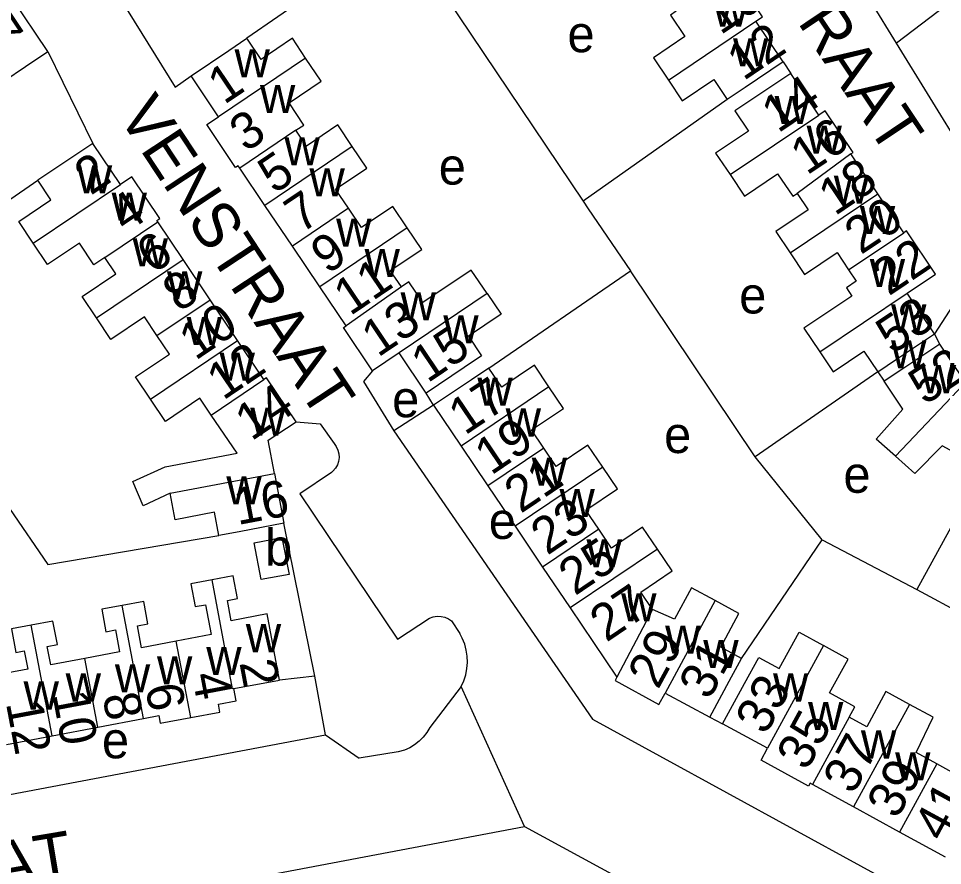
# Model space of a CAD drawing. Extents: x 158356 to 159894, y 383831 to 385260.
# Drawn here: x 158792.4 to 158893.5, y 384070.1 to 384162.8 of the extents above; entities that cross this region are included whole.
import ezdxf

# ---------------------------------------------------------------- set-up
doc = ezdxf.new("R2010")
doc.units = 0
for name, color, linetype in [('BLT_Basislijn', 7, 'Continuous'), ('BLT_Bebouwing', 7, 'Continuous'), ('BLT_Centroide', 7, 'Continuous'), ('BLT_Huisnummer', 7, 'Continuous'), ('BLT_Huisnummer_ tussenligend', 7, 'Continuous'), ('BLT_Onderdoorgang_en_onderverdeling', 7, 'Continuous'), ('BLT_Onderverdeling_panden', 7, 'Continuous'), ('BLT_Straatnaam', 7, 'Continuous'), ('BLT_Vlakafsluiter', 7, 'Continuous')]:
    doc.layers.add(name, color=color, linetype=linetype)

msp = doc.modelspace()

# ---------------------------------------------------------------- linework, layer by layer
at = {"layer": 'BLT_Basislijn'}
for p, q in [((158835.86, 384170.1), (158854.18, 384142.81)), ((158888.48, 384160.12), (158885.74, 384164.57)), ((158896.12, 384147.7), (158888.48, 384160.12)), ((158795.59, 384159.2), (158800.5, 384149.14)), ((158876.08, 384158.06), (158876.9, 384156.81)), ((158869.96, 384153.95), (158854.18, 384142.81)), ((158843.85, 384124.55), (158859.36, 384135.19)), ((158837.8, 384120.48), (158837.01, 384121.81)), ((158837.8, 384120.48), (158833.44, 384117.69)), ((158822.77, 384118.68), (158825.38, 384118.43)), ((158825.38, 384118.43), (158826.91, 384116.3)), ((158880.34, 384105.75), (158873, 384114.85)), ((158897.99, 384113.6), (158890.7, 384100.31)), ((158824.81, 384090.82), (158821.43, 384107.57)), ((158871.51, 384092.76), (158880.34, 384105.75)), ((158880.34, 384105.75), (158890.7, 384100.31)), ((158890.7, 384100.31), (158920.54, 384084.28)), ((158839.78, 384096.87), (158840.67, 384095.5)), ((158824.81, 384090.82), (158820.93, 384090.4)), ((158825.97, 384084.41), (158824.81, 384090.82)), ((158840.81, 384089.71), (158837.38, 384085.21)), ((158868.03, 384086.34), (158869.45, 384085.62)), ((158770.26, 384073.85), (158825.97, 384084.41)), ((158825.97, 384084.41), (158829.66, 384081.86)), ((158833.93, 384082.55), (158829.66, 384081.86))]:
    msp.add_line(p, q, dxfattribs=at)
for points in [[(158908.13, 384178.98), (158909.41, 384176.35), (158909.32, 384175.99), (158888.48, 384160.12)], [(158835.86, 384170.1), (158834.33, 384172.38), (158817.37, 384160.65)], [(158801.39, 384168.44), (158809.52, 384155.32), (158811.27, 384156.54)], [(158776.55, 384133.1), (158779.21, 384134.56), (158794.5, 384145.11)], [(158854.18, 384142.81), (158854.74, 384141.98), (158859.36, 384135.19)], [(158873, 384114.85), (158859.36, 384135.19)], [(158831.12, 384124.26), (158830.13, 384123.07), (158833.44, 384117.69)], [(158886.43, 384124.13), (158873, 384114.85)], [(158833.44, 384117.69), (158855.2, 384086.11), (158906.53, 384058.02)], [(158826.91, 384116.3), (158827.15, 384115.96), (158827.33, 384115.58), (158827.43, 384115.17), (158827.46, 384114.76), (158827.4, 384114.34), (158827.27, 384113.95), (158827.06, 384113.58), (158826.79, 384113.26), (158826.63, 384113.13)], [(158826.63, 384113.13), (158823.17, 384110.77), (158833.87, 384094.88), (158837.35, 384097.19)], [(158791.37, 384109.19), (158795.56, 384103.06), (158814.31, 384106.22)], [(158837.35, 384097.19), (158837.76, 384097.33), (158838.19, 384097.39), (158838.63, 384097.37), (158839.05, 384097.27), (158839.45, 384097.1), (158839.78, 384096.87)], [(158840.81, 384089.71), (158841.1, 384090.33), (158841.32, 384090.98), (158841.45, 384091.65), (158841.51, 384092.33), (158841.49, 384093.01), (158841.39, 384093.68), (158841.21, 384094.34), (158840.95, 384094.97), (158840.67, 384095.5)], [(158837.38, 384085.21), (158837.06, 384084.66), (158836.67, 384084.16), (158836.23, 384083.71), (158835.73, 384083.32), (158835.19, 384082.99), (158834.61, 384082.74), (158833.93, 384082.55)], [(158810.66, 384061.72), (158809.81, 384066.33), (158809.81, 384066.91), (158810.54, 384067.32), (158847.76, 384074.35)], [(158847.76, 384074.35), (158872.31, 384061.02)]]:
    msp.add_lwpolyline(points, dxfattribs=at)
at = {"layer": 'BLT_Bebouwing'}
for p, q in [((158795.59, 384159.2), (158788.57, 384169.69)), ((158876.08, 384158.06), (158873.09, 384162.52)), ((158814.27, 384152.07), (158811.27, 384156.54)), ((158879.97, 384152.25), (158876.9, 384156.81)), ((158803.52, 384144.66), (158800.5, 384149.14)), ((158886.44, 384143.61), (158883.5, 384147.99)), ((158819.35, 384142.36), (158816.6, 384146.44)), ((158889.29, 384139.37), (158886.44, 384143.61)), ((158822.35, 384137.9), (158819.35, 384142.36)), ((158801.82, 384136.66), (158807.62, 384140.55)), ((158810.4, 384136.42), (158807.62, 384140.55)), ((158825.35, 384133.45), (158822.35, 384137.9)), ((158813.34, 384132.04), (158810.4, 384136.42)), ((158828.23, 384129.18), (158825.35, 384133.45)), ((158892.63, 384128.3), (158889.65, 384132.74)), ((158816.34, 384127.56), (158813.34, 384132.04)), ((158893.24, 384127.17), (158892.63, 384128.3)), ((158819.22, 384123.29), (158816.34, 384127.56)), ((158896.02, 384122.99), (158893.24, 384127.17)), ((158834.04, 384126.22), (158831.12, 384124.26)), ((158837.01, 384121.81), (158834.04, 384126.22)), ((158886.43, 384124.13), (158887.13, 384123.11)), ((158837.8, 384120.48), (158840.81, 384116.02)), ((158840.81, 384116.02), (158843.76, 384111.65)), ((158820.4, 384113.01), (158821.43, 384107.57)), ((158843.76, 384111.65), (158846.72, 384107.25)), ((158846.72, 384107.25), (158849.74, 384102.77)), ((158849.74, 384102.77), (158852.76, 384098.3)), ((158852.76, 384098.3), (158857.88, 384090.7)), ((158863.16, 384088.98), (158868.03, 384086.34)), ((158801.06, 384085.24), (158806.06, 384086.18)), ((158874.36, 384082.94), (158869.45, 384085.62)), ((158796.05, 384084.3), (158801.06, 384085.24)), ((158791.05, 384083.35), (158796.05, 384084.3)), ((158883.77, 384076.51), (158879.27, 384078.97)), ((158888.82, 384073.75), (158883.77, 384076.51)), ((158893.84, 384071), (158888.82, 384073.75))]:
    msp.add_line(p, q, dxfattribs=at)
for points in [[(158873.09, 384162.52), (158873.83, 384163.02), (158870.65, 384167.75), (158870.36, 384167.55)], [(158864.38, 384163.62), (158863.75, 384163.19), (158865.32, 384160.84), (158861.87, 384158.52), (158863.51, 384156.08)], [(158811.27, 384156.54), (158815.41, 384159.33), (158817.37, 384160.65)], [(158823.8, 384158.49), (158822.35, 384160.65), (158818.93, 384158.34), (158817.37, 384160.65)], [(158790.77, 384155.97), (158793.15, 384157.57), (158795.59, 384159.2)], [(158822.74, 384150.58), (158823.61, 384151.16), (158821.98, 384153.58), (158825.51, 384155.96), (158823.8, 384158.49)], [(158876.08, 384158.06), (158871.93, 384155.28), (158869.96, 384153.95)], [(158876.9, 384156.81), (158872.76, 384154.02), (158870.79, 384152.7), (158872.27, 384150.5), (158868.68, 384148.09), (158870.27, 384145.74)], [(158863.51, 384156.08), (158865.03, 384153.81), (158868.49, 384156.14), (158869.96, 384153.95)], [(158883.5, 384147.99), (158883.75, 384148.15), (158880.67, 384152.73), (158879.97, 384152.25)], [(158816.6, 384146.44), (158816.42, 384146.71), (158816.13, 384146.52), (158812.98, 384151.2), (158814.27, 384152.07)], [(158828.91, 384148.8), (158827.32, 384151.17), (158823.9, 384148.86), (158822.74, 384150.58)], [(158800.5, 384149.14), (158796.35, 384146.36), (158794.5, 384145.11)], [(158828.5, 384142.05), (158827.08, 384144.14), (158830.5, 384146.44), (158828.91, 384148.8)], [(158807.62, 384140.55), (158807.52, 384140.7), (158807.84, 384140.92), (158804.77, 384145.5), (158803.52, 384144.66)], [(158870.27, 384145.74), (158871.85, 384143.38), (158875.47, 384145.81), (158877.12, 384143.36), (158877.6, 384143.68)], [(158793.98, 384138.24), (158792.4, 384140.59), (158795.92, 384142.96), (158794.5, 384145.11)], [(158877.6, 384143.68), (158878.81, 384141.89), (158875.26, 384139.51), (158876.84, 384137.15)], [(158834.93, 384139.9), (158833.34, 384142.25), (158829.91, 384139.95), (158828.5, 384142.05)], [(158834.28, 384133.43), (158833.07, 384135.23), (158836.51, 384137.55), (158834.93, 384139.9)], [(158889.65, 384132.74), (158892.76, 384134.84), (158889.59, 384139.56), (158889.29, 384139.37)], [(158801.82, 384136.66), (158800.63, 384135.86), (158799.03, 384138.24), (158795.55, 384135.9), (158793.98, 384138.24)], [(158876.84, 384137.15), (158878.42, 384134.8), (158881.97, 384137.19), (158883.24, 384135.3)], [(158800.9, 384130.04), (158799.32, 384132.38), (158803.02, 384134.87), (158801.82, 384136.66)], [(158843.67, 384132.71), (158841.93, 384135.28), (158836.64, 384131.72), (158835.11, 384133.99), (158834.28, 384133.43)], [(158883.24, 384135.3), (158884.08, 384134.05), (158883.01, 384133.33), (158883.6, 384132.44), (158878.35, 384128.91), (158880.09, 384126.32)], [(158843.67, 384132.71), (158845.19, 384130.44), (158841.62, 384128.03), (158843.07, 384125.89), (158841.15, 384124.6), (158837.01, 384121.81)], [(158807.52, 384128.12), (158806.15, 384130.16), (158802.47, 384127.69), (158800.9, 384130.04)], [(158831.12, 384124.26), (158827.94, 384128.99), (158828.23, 384129.18)], [(158806.81, 384121.16), (158805.17, 384123.6), (158808.88, 384126.09), (158807.52, 384128.12)], [(158880.09, 384126.32), (158881.56, 384124.14), (158884.91, 384126.39), (158886.43, 384124.13)], [(158843.85, 384124.55), (158841.95, 384123.27), (158837.8, 384120.48)], [(158850.43, 384122.5), (158848.84, 384124.86), (158845.26, 384122.45), (158843.85, 384124.55)], [(158822.77, 384118.68), (158819.53, 384123.5), (158819.22, 384123.29)], [(158888.37, 384114.89), (158886.25, 384116.78), (158889.17, 384120.04), (158887.13, 384123.11)], [(158849.88, 384115.78), (158848.52, 384117.78), (158852.03, 384120.14), (158850.43, 384122.5)], [(158813.45, 384119.41), (158812.2, 384121.24), (158808.45, 384118.72), (158806.81, 384121.16)], [(158808.98, 384110.85), (158806.01, 384109.47), (158804.9, 384112.15), (158808.43, 384113.75), (158816.3, 384115.24), (158813.45, 384119.41)], [(158820.4, 384113.01), (158819.71, 384116.65), (158822.77, 384118.68)], [(158856.32, 384113.72), (158854.71, 384116.11), (158851.23, 384113.77), (158849.88, 384115.78)], [(158897, 384114.14), (158893.5, 384116.04), (158890.48, 384113), (158888.37, 384114.89)], [(158855.89, 384106.92), (158854.48, 384109), (158857.93, 384111.33), (158856.32, 384113.72)], [(158814.31, 384106.22), (158813.83, 384108.76), (158809.53, 384107.95), (158808.98, 384110.85)], [(158821.43, 384107.57), (158816.51, 384106.64), (158814.31, 384106.22)], [(158862.31, 384104.73), (158860.69, 384107.13), (158857.29, 384104.83), (158855.89, 384106.92)], [(158861.76, 384098.13), (158860.48, 384100.02), (158863.92, 384102.34), (158862.31, 384104.73)], [(158820.93, 384090.4), (158819.57, 384097.63), (158815.64, 384096.89), (158815.23, 384099.1), (158816.34, 384099.31), (158815.87, 384101.81), (158813.56, 384101.37)], [(158813.56, 384101.37), (158811.24, 384100.93), (158811.71, 384098.44), (158812.82, 384098.65), (158813.44, 384095.37), (158809.64, 384094.65)], [(158868.64, 384099.09), (158866.05, 384100.49), (158864.19, 384097.07), (158861.76, 384098.13)], [(158809.64, 384094.65), (158805.84, 384093.93), (158805.39, 384096.34), (158806.53, 384096.55), (158806.07, 384099.01), (158803.72, 384098.57)], [(158871.51, 384092.76), (158869.24, 384094), (158871.24, 384097.68), (158868.64, 384099.09)], [(158803.72, 384098.57), (158801.48, 384098.15), (158801.94, 384095.69), (158802.97, 384095.88), (158803.43, 384093.48), (158799.64, 384092.76)], [(158799.64, 384092.76), (158795.89, 384092.06), (158795.51, 384094.07), (158796.62, 384094.28), (158796.14, 384096.84), (158793.77, 384096.4)], [(158793.77, 384096.4), (158791.59, 384095.99), (158792.07, 384093.42), (158792.99, 384093.6), (158793.37, 384091.58), (158789.63, 384090.88)], [(158869.45, 384085.62), (158871.85, 384090.01), (158873.41, 384092.88), (158875.65, 384091.65), (158877.82, 384095.63), (158880.5, 384094.17)], [(158883.3, 384086.34), (158883.92, 384087.48), (158881.15, 384088.99), (158883.18, 384092.7), (158880.5, 384094.17)], [(158868.03, 384086.34), (158870.41, 384090.74), (158871.51, 384092.76)], [(158857.88, 384090.7), (158857.69, 384090.34), (158862.48, 384087.74), (158863.16, 384088.98)], [(158815.94, 384089.46), (158820.93, 384090.4)], [(158811.22, 384086.3), (158814.41, 384086.9), (158814.25, 384087.76), (158816.2, 384088.13), (158815.94, 384089.46)], [(158889.91, 384087.73), (158887.33, 384089.13), (158885.23, 384085.28), (158883.3, 384086.34)], [(158892.9, 384081.21), (158890.62, 384082.46), (158892.48, 384086.32), (158889.91, 384087.73)], [(158806.06, 384086.18), (158807.73, 384086.5), (158807.89, 384085.67), (158811.22, 384086.3)], [(158900.01, 384082.27), (158897.26, 384083.78), (158895.18, 384079.96), (158892.9, 384081.21)], [(158879.27, 384078.97), (158879.03, 384079.1), (158878.86, 384078.79), (158873.67, 384081.63), (158874.36, 384082.94)]]:
    msp.add_lwpolyline(points, dxfattribs=at)
msp.add_lwpolyline([(158818.17, 384105.42), (158821.21, 384106), (158821.98, 384101.97), (158818.93, 384101.39)], close=True, dxfattribs=at)
at = {"layer": 'BLT_Onderdoorgang_en_onderverdeling'}
for points in [[(158886.43, 384124.13), (158888.48, 384125.51), (158892.63, 384128.3)], [(158893.24, 384127.17), (158889.07, 384124.4), (158887.13, 384123.11)]]:
    msp.add_lwpolyline(points, dxfattribs=at)
at = {"layer": 'BLT_Onderverdeling_panden'}
for p, q in [((158863.51, 384156.08), (158873.09, 384162.52)), ((158823.8, 384158.49), (158814.27, 384152.07)), ((158870.27, 384145.74), (158879.97, 384152.25)), ((158822.74, 384150.58), (158816.6, 384146.44)), ((158828.91, 384148.8), (158819.35, 384142.36)), ((158883.5, 384147.99), (158877.6, 384143.68)), ((158793.98, 384138.24), (158803.52, 384144.66)), ((158876.84, 384137.15), (158886.44, 384143.61)), ((158828.5, 384142.05), (158822.35, 384137.9)), ((158834.93, 384139.9), (158825.35, 384133.45)), ((158883.24, 384135.3), (158889.29, 384139.37)), ((158800.9, 384130.04), (158810.4, 384136.42)), ((158834.28, 384133.43), (158828.23, 384129.18)), ((158843.67, 384132.71), (158834.04, 384126.22)), ((158880.09, 384126.32), (158889.65, 384132.74)), ((158807.52, 384128.12), (158813.34, 384132.04)), ((158806.81, 384121.16), (158816.34, 384127.56)), ((158813.45, 384119.41), (158819.22, 384123.29)), ((158850.43, 384122.5), (158840.81, 384116.02)), ((158888.37, 384114.89), (158896.02, 384122.99)), ((158849.88, 384115.78), (158843.76, 384111.65)), ((158808.98, 384110.85), (158820.4, 384113.01)), ((158856.32, 384113.72), (158846.72, 384107.25)), ((158855.89, 384106.92), (158849.74, 384102.77)), ((158862.31, 384104.73), (158852.76, 384098.3)), ((158868.64, 384099.09), (158863.16, 384088.98)), ((158806.06, 384086.18), (158803.72, 384098.57)), ((158861.76, 384098.13), (158857.88, 384090.7)), ((158796.05, 384084.3), (158793.77, 384096.4)), ((158880.5, 384094.17), (158874.36, 384082.94)), ((158801.06, 384085.24), (158799.64, 384092.76)), ((158889.91, 384087.73), (158883.77, 384076.51)), ((158883.3, 384086.34), (158879.27, 384078.97)), ((158892.9, 384081.21), (158888.82, 384073.75))]:
    msp.add_line(p, q, dxfattribs=at)
for points in [[(158815.94, 384089.46), (158815.81, 384089.44), (158813.56, 384101.37)], [(158811.22, 384086.3), (158809.64, 384094.65)]]:
    msp.add_lwpolyline(points, dxfattribs=at)
at = {"layer": 'BLT_Vlakafsluiter'}
for p, q in [((158900.74, 384140.84), (158892.63, 384128.3)), ((158847.76, 384074.35), (158840.81, 384089.71))]:
    msp.add_line(p, q, dxfattribs=at)

# ---------------------------------------------------------------- texts
at = {"layer": 'BLT_Centroide'}
for s, p in [('w', (158868.4, 384161.91)), ('e', (158852.46, 384159.13)), ('w', (158870.59, 384157.59)), ('w', (158816.02, 384156.38)), ('w', (158818.8, 384152.47)), ('w', (158875.13, 384151.28)), ('w', (158878.64, 384148.03)), ('w', (158821.48, 384146.75)), ('e', (158838.37, 384144.64)), ('w', (158798.76, 384143.69)), ('w', (158824.22, 384143.34)), ('w', (158881.62, 384142.56)), ('w', (158802.56, 384140.69)), ('w', (158884.47, 384139.22)), ('w', (158827.14, 384137.84)), ('w', (158804.86, 384135.69)), ('w', (158830.25, 384134.53)), ('w', (158885.56, 384133.42)), ('w', (158808.62, 384132.06)), ('e', (158871.26, 384130.53)), ('w', (158834.19, 384129.78)), ('w', (158887.89, 384128.44)), ('w', (158810.77, 384127.06)), ('w', (158838.87, 384127.25)), ('w', (158887.89, 384124.51)), ('w', (158814.38, 384123.16)), ('w', (158891.14, 384121.8)), ('w', (158842.6, 384120.44)), ('e', (158833.27, 384119.17)), ('w', (158817.73, 384117.16)), ('w', (158845.7, 384117.06)), ('e', (158863.04, 384115.25)), ('w', (158848.55, 384111.69)), ('e', (158882.67, 384110.9)), ('w', (158815.12, 384109.62)), ('w', (158851.59, 384108.25)), ('e', (158843.85, 384105.85)), ('b', (158819.36, 384102.93)), ('w', (158854.55, 384102.72)), ('w', (158858.34, 384096.81)), ('w', (158817.25, 384093.45)), ('w', (158863.16, 384093.27)), ('w', (158867.33, 384091.7)), ('w', (158812.92, 384090.95)), ('w', (158807.53, 384089.92)), ('w', (158802.92, 384089.05)), ('w', (158797.53, 384088.05)), ('w', (158874.97, 384088.05)), ('w', (158792.92, 384087.17)), ('w', (158878.8, 384084.94)), ('e', (158801.5, 384081.83)), ('w', (158884.59, 384081.81)), ('w', (158888.33, 384079.42))]:
    msp.add_text(s, height=4, dxfattribs=at).set_placement(p)
at = {"layer": 'BLT_Huisnummer'}
for s, rotation, p in [('187', 303.7833, (158784.78, 384166.41)), ('12', 33.9028, (158871.73, 384155.94)), ('1', 33.9775, (158814.88, 384153.33)), ('14', 33.9028, (158875.51, 384150.21)), ('2', 33.9071, (158800.27, 384143.4)), ('5', 33.9775, (158820.37, 384143.55)), ('18', 33.9028, (158881.73, 384141.15)), ('6', 33.9071, (158807.07, 384134.78)), ('9', 33.9775, (158826.16, 384134.75)), ('53', 33.903, (158888.02, 384125.98)), ('10', 33.9071, (158811.73, 384125.32)), ('15', 33.9775, (158837.14, 384122.85)), ('52', 33.6456, (158891.57, 384120.42)), ('17', 33.9775, (158841.23, 384117.13)), ('14', 33.9071, (158817.86, 384116.5)), ('21', 33.9775, (158847.34, 384108.57)), ('16', 10.7077, (158816.36, 384107.36)), ('25', 33.9775, (158853.28, 384099.57)), ('31', 61.5029, (158867.97, 384088.09)), ('2', 280.6809, (158816.54, 384092.31)), ('33', 61.5029, (158874.17, 384084.27)), ('6', 280.6809, (158806.22, 384089.68)), ('10', 280.6809, (158796.05, 384088.87)), ('37', 61.5029, (158883.75, 384077.75)), ('41', 61.5029, (158893.66, 384072.53))]:
    msp.add_text(s, height=4, rotation=rotation, dxfattribs=at).set_placement(p)
at = {"layer": 'BLT_Huisnummer_ tussenligend'}
for s, rotation, p in [('10', 33.9028, (158869.21, 384160.96)), ('3', 33.9775, (158817.26, 384148.12)), ('16', 33.9028, (158878.67, 384145.6)), ('4', 33.9071, (158804.11, 384139.26)), ('7', 33.9775, (158823.28, 384139.22)), ('20', 33.9028, (158884.58, 384136.9)), ('22', 33.9028, (158887.63, 384132.38)), ('11', 33.9775, (158828.66, 384130.2)), ('8', 33.9071, (158809.93, 384130.59)), ('13', 33.9775, (158831.71, 384125.66)), ('12', 33.9071, (158814.77, 384120.96)), ('19', 33.9775, (158844.1, 384112.75)), ('23', 33.9775, (158850.24, 384103.99)), ('27', 33.9775, (158856.71, 384094.47)), ('29', 61.5029, (158862.38, 384089.27)), ('4', 280.6809, (158811.34, 384090.95)), ('8', 280.6809, (158801.55, 384088.68)), ('12', 280.6809, (158790.98, 384087.87)), ('35', 61.5029, (158878.67, 384080.35)), ('39', 61.5029, (158888.55, 384075.06))]:
    msp.add_text(s, height=4, rotation=rotation, dxfattribs=at).set_placement(p)
at = {"layer": 'BLT_Straatnaam'}
for s, height, rotation, p in [('DOESBURGSTRAAT', 4.9999, 303.7433, (158851.58, 384201.35)), ('VENSTRAAT', 5, 303.3492, (158803.16, 384152.23)), ('KOOTWIJKSTRAAT', 5, 9.554, (158738.09, 384058.84))]:
    msp.add_text(s, height=height, rotation=rotation, dxfattribs=at).set_placement(p)

doc.saveas('drawing.dxf')
